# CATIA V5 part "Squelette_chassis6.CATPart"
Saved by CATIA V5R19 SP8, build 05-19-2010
Part number: Squelette_chassis6
Bounding box of the stored display mesh (mm): x 30 to 50, y -143.861 to 82, z 50 to 105
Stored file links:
  G:\EU_thinkMotion\CFAO_2010\MMS_groupe2\MMS_groupe2\A reprendre\jcauchy\Squelette_chassis6.CATPart
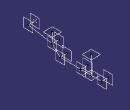
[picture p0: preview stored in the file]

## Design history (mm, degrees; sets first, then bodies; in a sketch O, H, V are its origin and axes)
Parameters
  `Séparationfixation_chassis6` = 120 mm
  Separationroue_chassis6 = 64 mm
  Longueurfixation_chassis6 = 20 mm
  Hauteurrouefixation_chassis6 = 55 mm
Set1
  Point1: (50, 50, 50)
  Plane1: type OffsetPt, RefPlane xy-plane, RefPoint Point1
  Line1: type Normal, RefPoint Point1, RefSkin Plane1, Start 55 {= Hauteurrouefixation_chassis6}, End 0
  Line2: type Angle, RefPoint vertex of Line1, Curve Line1, Support yz-plane, Start -96 {= -Separationroue_chassis6 *2+(Separationroue_chassis6 /2)}, End 32 {= Separationroue_chassis6 /2}, Angle -90
  Point2: type OnCurve, Support Line2, Ratio 0.5
  Line3: type Angle, RefPoint Point2, Curve Line2, Support xy-plane, Start -20 {= -Longueurfixation_chassis6}, End 0, Angle -90
  Line4: type Angle, RefPoint vertex of Line2, Curve Line2, Support xy-plane, Start -20 {= -Longueurfixation_chassis6}, End 0, Angle -90
  Plane2: type Normal, Curve Line3, RefPoint vertex of Line3
  Plane3: type Normal, Curve Line3, RefPoint vertex of Line3
  Plane4: type Normal, Curve Line4, RefPoint vertex of Line4
  Plane5: type Normal, Curve Line4, RefPoint vertex of Line4
  Line5: type Angle, RefPoint vertex of Line2, Curve Line2, Support yz-plane, Start 0, End -33.9411 {= -(`Séparationfixation_chassis6` -(Separationroue_chassis6 +Separationroue_chassis6 /2))/cos(45deg)}, Angle -45 {= -45deg}
  Line6: type Angle, RefPoint vertex of Line5, Curve Line5, Support Plane3, Start 0, End -75, Angle 35
  Line7: type PtDir, RefPoint vertex of Line5, Direction Line1, Start 0, End 31 {= Hauteurrouefixation_chassis6 -(`Séparationfixation_chassis6` -(Separationroue_chassis6 +Separationroue_chassis6 /2))*tan(45deg)}
  Line8: type PtDir, RefPoint vertex of Line5, Direction Line3, Start -20 {= -Longueurfixation_chassis6}, End 0
  Line9: type PtDir, RefPoint vertex of Line6, Direction Line3, Start -20 {= -Longueurfixation_chassis6}, End 0
  Plane6: type Normal, Curve {inverselocal InverseElem Line9}, RefPoint vertex of Line9
  Plane7: type Normal, Curve {inverselocal InverseElem Line9}, RefPoint vertex of Line9
  Plane8: type Normal, Curve {inverselocal InverseElem Line8}, RefPoint vertex of Line8
  Plane9: type Normal, Curve {inverselocal InverseElem Line8}, RefPoint vertex of Line8
  Plane10: type Normal, Curve Line7, RefPoint vertex of Line7
  Line10: type PtDir, RefPoint vertex of Line2, Direction Line3, Start -20 {= -Longueurfixation_chassis6}, End 0
  Plane11: type Normal, Curve Line10, RefPoint vertex of Line10
  Plane12: type Normal, Curve Line10, RefPoint vertex of Line10
  Plane13: type Normal, Curve Line1, RefPoint vertex of Line1
  Point3: type OnCurve, Support Line9, Ratio 1
Body1 (main body)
